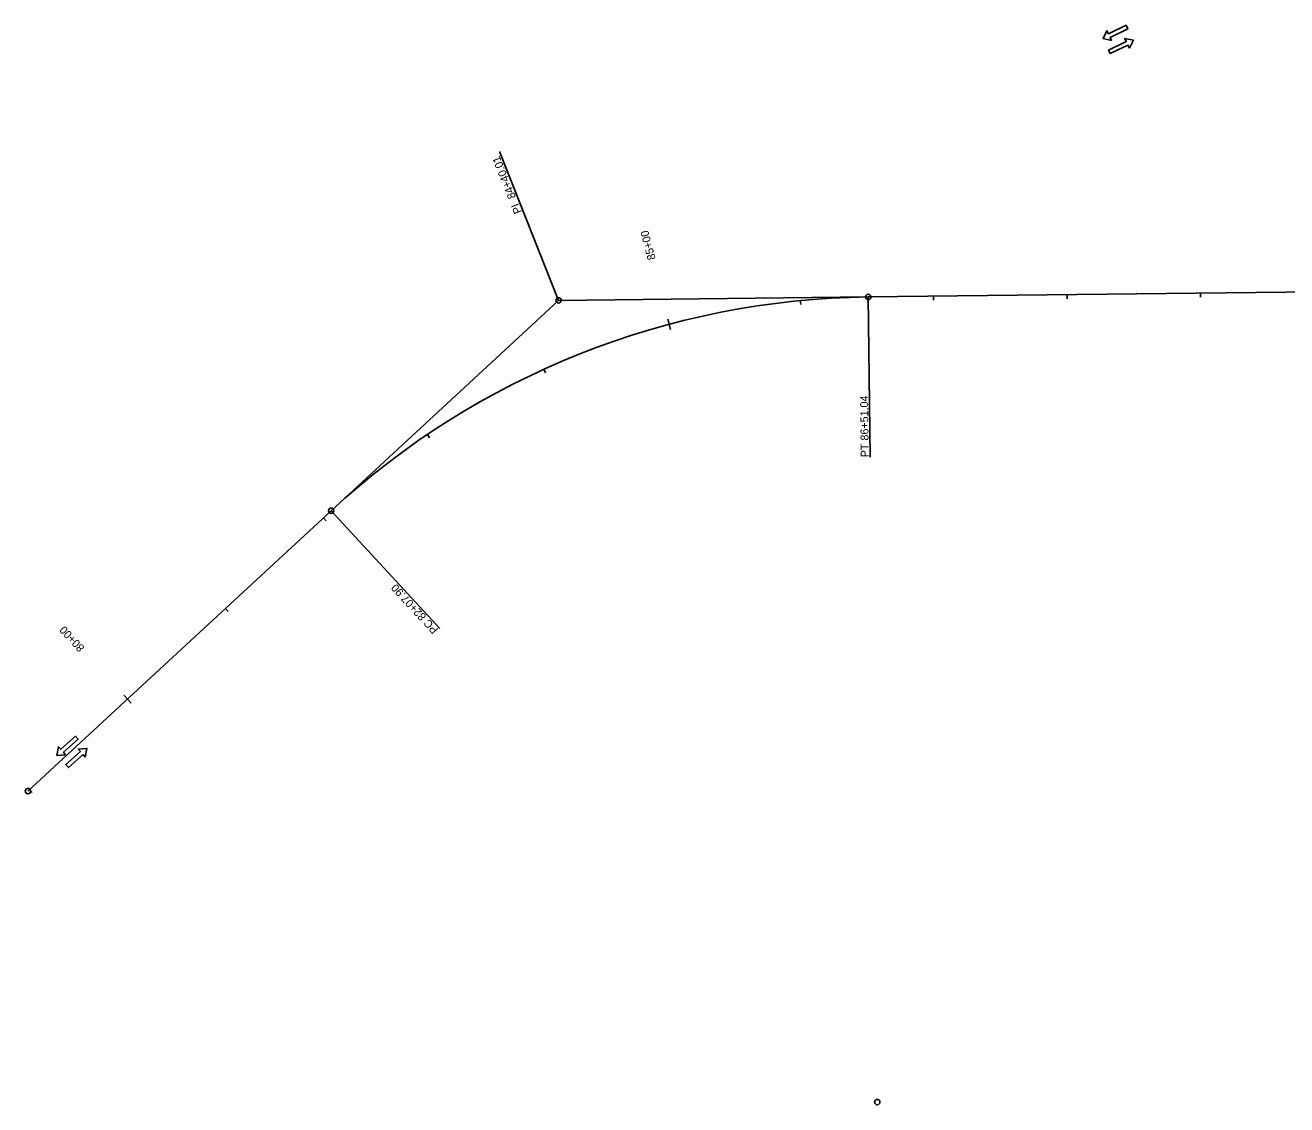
# Model space of a CAD drawing. Extents: x 1710760 to 1712674, y 548603 to 551099.
# Drawn here: x 1710760 to 1711705, y 548603 to 549412 of the extents above; entities that cross this region are included whole.
import ezdxf

# ---------------------------------------------------------------- set-up
doc = ezdxf.new("R2010")
doc.units = 0
for name, color, linetype in [('R_Horz Alg', 7, 'Continuous'), ('R_Horz Alg Annot', 7, 'Continuous'), ('R_MOT', 7, 'Continuous')]:
    doc.layers.add(name, color=color, linetype=linetype)

msp = doc.modelspace()

# ---------------------------------------------------------------- linework, layer by layer
at = {"layer": 'R_Horz Alg'}
for p, q in [((1711391.77, 549208.53), (1711733, 549212.35)), ((1710761.95, 548838.38), (1710989.21, 549048.39))]:
    msp.add_line(p, q, dxfattribs=at)
msp.add_arc((1711398.54, 548605.45), 603.11, 90.64281, 132.74131, dxfattribs=at)
at = {"layer": 'R_Horz Alg Annot'}
for p, q in [((1710989.21, 549048.39), (1711159.68, 549205.92)), ((1711159.68, 549205.92), (1711391.77, 549208.53))]:
    msp.add_line(p, q, dxfattribs=at)
for points in [[(1711159.68, 549205.92), (1711115.32, 549317.42)], [(1711341.11, 549202.81), (1711340.82, 549205.8)], [(1711391.77, 549208.53), (1711393.12, 549088.53)], [(1711440.76, 549206.08), (1711440.73, 549209.07)], [(1711540.75, 549207.2), (1711540.72, 549210.2)], [(1711640.75, 549208.32), (1711640.71, 549211.32)], [(1711241.49, 549191.9), (1711243.56, 549184.17)], [(1711149.75, 549151.57), (1711148.51, 549154.3)], [(1711063.03, 549103.01), (1711061.35, 549105.5)], [(1710985.45, 549040.83), (1710983.41, 549043.03)], [(1710989.21, 549048.39), (1711070.66, 548960.26)], [(1710912, 548972.96), (1710909.97, 548975.16)], [(1710833.81, 548910.23), (1710839.24, 548904.35)], [(1710765.12, 548837.22), (1710763.08, 548839.42)]]:
    msp.add_lwpolyline(points, dxfattribs=at)
for centre in [(1711159.68, 549205.92), (1711391.77, 549208.53), (1710989.21, 549048.39), (1710761.95, 548838.38), (1711398.54, 548605.45)]:
    msp.add_circle(centre, 2, dxfattribs=at)
at = {"layer": 'R_MOT'}
for points in [[(1711574.12, 549400.72), (1711567.7, 549402.08), (1711570.65, 549407.93), (1711571.73, 549405.68), (1711584.99, 549412.05), (1711586.29, 549409.35), (1711573.03, 549402.97)], [(1711587.48, 549394.9), (1711590.42, 549400.75), (1711584.01, 549402.11), (1711585.1, 549399.85), (1711571.84, 549393.48), (1711573.14, 549390.78), (1711586.4, 549397.15)], [(1710790.22, 548865.61), (1710783.68, 548865.17), (1710784.93, 548871.61), (1710786.58, 548869.73), (1710797.62, 548879.46), (1710799.6, 548877.21), (1710788.57, 548867.48)], [(1710804.96, 548863.88), (1710806.21, 548870.32), (1710799.67, 548869.89), (1710801.32, 548868.01), (1710790.28, 548858.28), (1710792.27, 548856.03), (1710803.31, 548865.76)]]:
    msp.add_lwpolyline(points, close=True, dxfattribs=at)

# ---------------------------------------------------------------- texts
at = {"layer": 'R_Horz Alg Annot'}
for s, rotation, p in [('PI  84+40.01', 111.69206, (1711132.24, 549272.19)), ('85+00', 104.99186, (1711232.49, 549237.11)), ('PT 86+51.04', 90.64281, (1711392.12, 549088.52)), ('PC 82+07.90', 132.74131, (1711069.92, 548959.58)), ('80+00', 132.74131, (1710804.79, 548946.05))]:
    msp.add_text(s, height=6, rotation=rotation, dxfattribs=at).set_placement(p)

doc.saveas('drawing.dxf')
